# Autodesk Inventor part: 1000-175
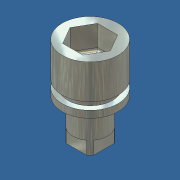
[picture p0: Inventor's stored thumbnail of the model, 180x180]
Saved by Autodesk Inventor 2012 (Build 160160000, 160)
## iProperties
Created: 2007-03
Part Number: 1000-175
Document SubType Name: Modeling
Designer: Andy Moles
Material: Steel
Mass: 20.2349 g
Surface Area: 20.3118 cm^2
Volume: 2.57769 cm^3
Density: 7.85 g/cm^3
Author: Andy Moles
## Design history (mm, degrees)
feature "Base1"
body "Solid1"
